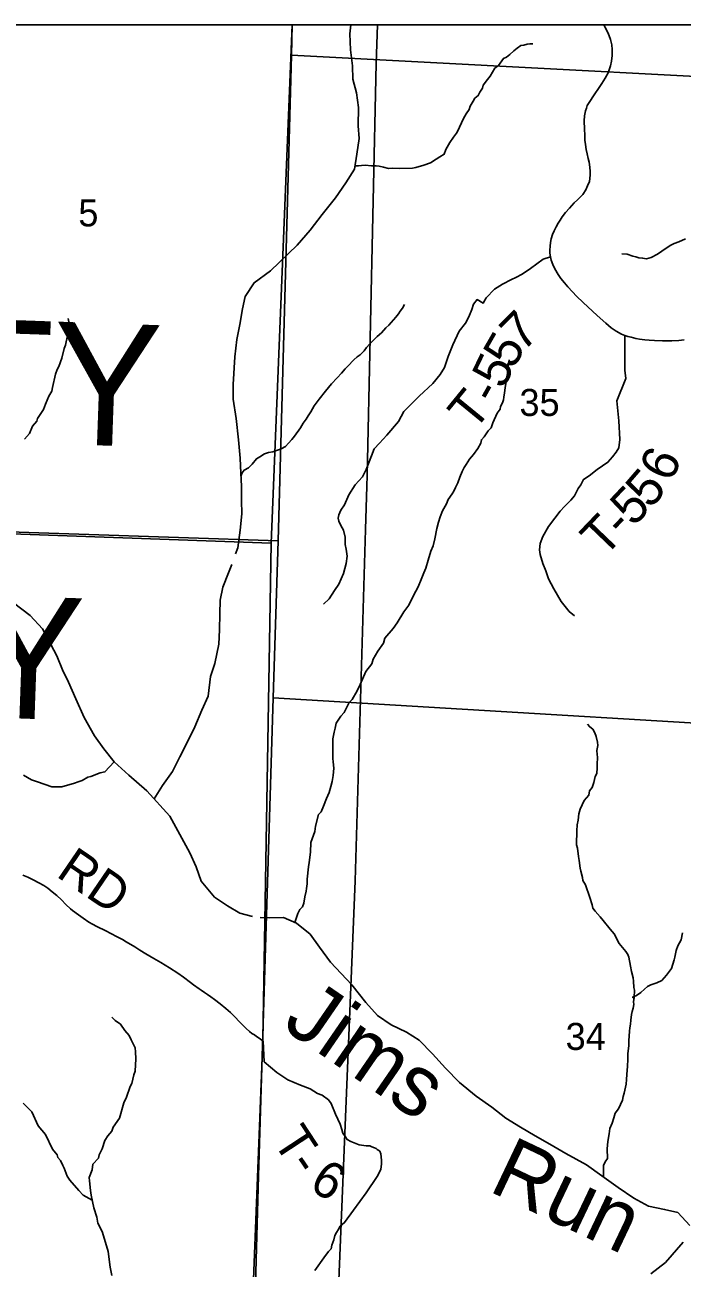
# Model space of a CAD drawing. Extents: x 6.3 to 40.3, y 9 to 31.
# Drawn here: x 12.585 to 13.605, y 28.019 to 29.946 of the extents above; entities that cross this region are included whole.
import ezdxf

# ---------------------------------------------------------------- set-up
doc = ezdxf.new("R2010")
doc.units = 0
for name, color, linetype in [('Default', 7, 'Continuous'), ('GM_X_Corporation', 7, 'Continuous'), ('GM_X_County_Text', 7, 'Continuous'), ('GM_X_Minor_River', 7, 'Continuous'), ('GM_X_Minor_River_Text', 7, 'Continuous'), ('GM_X_Section', 7, 'Continuous'), ('GM_X_Section_Text', 7, 'Continuous'), ('GM_X_State_Route', 7, 'Continuous'), ('GM_X_Township_Road', 7, 'Continuous'), ('GM_X_Township_Road_Text', 7, 'Continuous'), ('SH_Cut_Line', 7, 'Continuous'), ('SH_Data', 7, 'Continuous')]:
    doc.layers.add(name, color=color, linetype=linetype)

msp = doc.modelspace()

# ---------------------------------------------------------------- linework, layer by layer
at = {"layer": 'Default'}
for points in [[(13.1323, 29.9457), (8.4446, 29.9457), (8.4446, 27.9161), (8.9627, 27.9002), (9.9314, 27.8681), (10.145, 27.8635), (10.7129, 27.8423), (11.7175, 27.8106), (12.5872, 27.7766), (13.0625, 27.76), (13.0974, 28.6191), (13.1136, 29.1637), (13.1156, 29.231), (13.116, 29.2473), (13.13, 29.8856)], [(12.9998, 29.9457), (8.4446, 29.9457), (8.4446, 29.2958), (8.8673, 29.2829), (9.8361, 29.2507), (10.0496, 29.2462), (10.6176, 29.225), (11.6221, 29.1933), (12.4918, 29.1593), (12.9672, 29.1426)]]:
    msp.add_lwpolyline(points, close=True, dxfattribs=at)
for points in [[(13.8699, 27.9843), (13.9229, 28.0334), (14.1255, 28.1814), (14.1838, 28.2048), (14.2088, 28.2297), (14.3175, 28.3072), (14.3656, 28.3529), (14.5068, 28.5239), (14.7136, 28.6814), (14.8068, 28.7324), (14.9534, 28.8297), (15.2353, 29.0934), (15.2446, 29.1038), (15.2446, 29.9457), (12.9998, 29.9457), (12.9672, 29.1426), (12.9544, 28.3711), (12.9197, 27.4857)], [(15.2446, 27.6302), (15.2446, 29.9457), (13.1323, 29.9457), (13.13, 29.8856), (13.116, 29.2473), (13.1156, 29.231), (13.1136, 29.1637), (13.0974, 28.6191), (13.0625, 27.76)], [(12.5156, 26.6082), (12.5871, 26.6738), (12.6705, 26.7404), (12.7595, 26.8013), (12.8444, 26.8649), (12.9035, 26.9144), (12.9197, 27.4857), (12.9544, 28.3711), (12.9672, 29.1426), (12.4918, 29.1593)]]:
    msp.add_lwpolyline(points, dxfattribs=at)
at = {"layer": 'GM_X_Corporation'}
for points in [[(13, 29.9457), (12.3853, 29.9457), (12.3591, 29.1669), (12.9779, 29.1462), (12.9985, 29.8988)], [(13.9997, 29.9457), (13, 29.9457), (12.9985, 29.8988), (13.9983, 29.8461)]]:
    msp.add_lwpolyline(points, close=True, dxfattribs=at)
at = {"layer": 'GM_X_Minor_River'}
for points in [[(12.9121, 29.1259), (12.9155, 29.1352), (12.9193, 29.1628), (12.9216, 29.1881), (12.9212, 29.2088), (12.9212, 29.2307), (12.9201, 29.2508), (12.9193, 29.2742), (12.9167, 29.3025), (12.9129, 29.3357), (12.9084, 29.3655), (12.9084, 29.3886), (12.911, 29.4312), (12.914, 29.458), (12.9186, 29.4814), (12.9228, 29.5056), (12.9269, 29.5248), (12.9406, 29.546), (12.9663, 29.5645), (13.0076, 29.6045), (13.0276, 29.6275), (13.0462, 29.6517), (13.067, 29.6777), (13.0829, 29.7008), (13.0962, 29.7219), (13.1003, 29.7453), (13.1037, 29.7698), (13.1022, 29.7891), (13.1026, 29.8178), (13.0996, 29.8404), (13.0939, 29.8616), (13.0931, 29.882), (13.0901, 29.9069), (13.0893, 29.9318), (13.0907, 29.9457)], [(13.0971, 29.7273), (13.0973, 29.7274), (13.1026, 29.7275), (13.1075, 29.728), (13.1132, 29.7281), (13.1227, 29.7272), (13.1299, 29.727), (13.1349, 29.7267), (13.1413, 29.725), (13.1494, 29.7232), (13.1547, 29.7234), (13.1664, 29.7232), (13.1865, 29.7237), (13.1918, 29.7246), (13.2039, 29.7283), (13.2141, 29.7319), (13.223, 29.7374), (13.229, 29.7414), (13.2354, 29.7453), (13.2383, 29.7526), (13.2441, 29.7634), (13.25, 29.7715), (13.2548, 29.7777), (13.2573, 29.7827), (13.2591, 29.7873), (13.2624, 29.7938), (13.2657, 29.8007), (13.2697, 29.808), (13.2745, 29.8146), (13.2759, 29.8196), (13.2806, 29.8276), (13.2832, 29.8319), (13.2884, 29.8362), (13.291, 29.8412), (13.295, 29.8477), (13.296, 29.8523), (13.3027, 29.8608), (13.3071, 29.8662), (13.3141, 29.8785), (13.3197, 29.8825), (13.3274, 29.8937), (13.3323, 29.8957), (13.3375, 29.9), (13.3434, 29.9054), (13.349, 29.9097), (13.3543, 29.9136), (13.3592, 29.9145), (13.3641, 29.9158), (13.3683, 29.9162), (13.3732, 29.9163)], [(13.6098, 29.6139), (13.5993, 29.6095), (13.5925, 29.6067), (13.5861, 29.6039), (13.5734, 29.5949), (13.5663, 29.5902), (13.5566, 29.5854), (13.5494, 29.5829), (13.5433, 29.5843), (13.5376, 29.5846), (13.533, 29.586), (13.5281, 29.5874), (13.5196, 29.5902), (13.5113, 29.5908)], [(12.9203, 29.2462), (12.9221, 29.2515), (12.9251, 29.2557), (12.9318, 29.2593), (12.9378, 29.2648), (12.9444, 29.2733), (12.9497, 29.2764), (12.9568, 29.2808), (12.9632, 29.2828), (12.97, 29.2841), (12.9772, 29.2866), (12.9828, 29.2886), (12.9896, 29.2925), (12.994, 29.2972), (12.9992, 29.303), (13.0036, 29.3084), (13.0125, 29.3212), (13.0168, 29.3285), (13.0213, 29.3347), (13.0246, 29.3397), (13.0286, 29.3459), (13.0337, 29.3551), (13.0415, 29.3655), (13.0514, 29.3779), (13.061, 29.3895), (13.0696, 29.3988), (13.0763, 29.4058), (13.0818, 29.4124), (13.0859, 29.4167), (13.0952, 29.4264), (13.1007, 29.4315), (13.1052, 29.4346), (13.1112, 29.4404), (13.1152, 29.4455), (13.1204, 29.4513), (13.1315, 29.4629), (13.1383, 29.4684), (13.1449, 29.4762), (13.1498, 29.4801), (13.1605, 29.4929), (13.1649, 29.4979), (13.1675, 29.5021), (13.1708, 29.5068), (13.1741, 29.5122)], [(12.5844, 29.3035), (12.5921, 29.3125), (12.5968, 29.3236), (12.6039, 29.3313), (12.6049, 29.3355), (12.6141, 29.3494), (12.6173, 29.3579), (12.6224, 29.3701), (12.6271, 29.3778), (12.6278, 29.3839), (12.6326, 29.4042), (12.6351, 29.4118), (12.6381, 29.4165), (12.6423, 29.4291), (12.6462, 29.4444), (12.648, 29.4494), (12.6514, 29.4643), (12.6532, 29.4719), (12.6538, 29.4765), (12.6537, 29.4807), (12.6532, 29.4856), (12.6524, 29.4905)], [(13.004, 28.5548), (13.0088, 28.5685), (13.0117, 28.5747), (13.0158, 28.5786), (13.018, 28.5843), (13.0192, 28.5946), (13.0217, 28.603), (13.022, 28.6072), (13.023, 28.6144), (13.0232, 28.6217), (13.0251, 28.6407), (13.0261, 28.6476), (13.028, 28.6636), (13.0288, 28.6784), (13.0349, 28.6957), (13.0358, 28.7041), (13.0404, 28.7217), (13.0448, 28.7263), (13.0484, 28.7351), (13.0531, 28.7467), (13.0571, 28.7559), (13.0599, 28.7651), (13.0616, 28.7731), (13.0633, 28.7822), (13.0642, 28.7937), (13.0636, 28.8035), (13.0631, 28.8088), (13.0628, 28.8267), (13.0629, 28.8392), (13.0649, 28.8496), (13.0663, 28.856), (13.068, 28.8637), (13.0754, 28.8741), (13.0806, 28.8799), (13.0882, 28.8953), (13.0926, 28.9), (13.1007, 28.9135), (13.1054, 28.9234), (13.1141, 28.9434), (13.1233, 28.9554), (13.1254, 28.9627), (13.1328, 28.975), (13.1412, 28.9873), (13.1437, 28.995), (13.1563, 29.0101), (13.1625, 29.019), (13.1732, 29.0363), (13.1809, 29.0464), (13.1882, 29.0614), (13.1951, 29.0748), (13.1998, 29.0863), (13.2041, 29.0963), (13.207, 29.1036), (13.2105, 29.1162), (13.2151, 29.13), (13.2187, 29.1385), (13.2208, 29.1492), (13.2242, 29.1652), (13.227, 29.1751), (13.2291, 29.1832), (13.2331, 29.1924), (13.2393, 29.2035), (13.2415, 29.21), (13.2477, 29.2189), (13.2507, 29.2232), (13.2532, 29.2286), (13.2565, 29.2358), (13.2597, 29.245), (13.2633, 29.2535), (13.2666, 29.2596), (13.2695, 29.2646), (13.2746, 29.2727), (13.2809, 29.2801), (13.2879, 29.289), (13.2923, 29.2975), (13.2933, 29.3028), (13.2974, 29.3075), (13.304, 29.3167), (13.3085, 29.3214), (13.311, 29.329), (13.3175, 29.344), (13.3223, 29.3502), (13.3229, 29.3544), (13.3258, 29.3602), (13.3276, 29.3644), (13.3279, 29.3689), (13.3293, 29.3754), (13.3303, 29.3831), (13.3313, 29.3899), (13.3322, 29.3975), (13.3336, 29.4056), (13.3338, 29.4105), (13.3361, 29.4265)], [(12.7856, 28.7463), (12.7985, 28.7667), (12.814, 28.7886), (12.8254, 28.8112), (12.8383, 28.8365), (12.8489, 28.8577), (12.8595, 28.8834), (12.8697, 28.9053), (12.8731, 28.9358), (12.8799, 28.9562), (12.886, 28.9857), (12.8871, 29.008), (12.8875, 29.0329), (12.8879, 29.054), (12.892, 29.0744), (12.9011, 29.0963), (12.906, 29.1096)], [(12.9381, 28.5637), (12.9188, 28.5688), (12.8995, 28.5805), (12.8795, 28.5937), (12.8587, 28.6186), (12.8511, 28.6409), (12.8409, 28.6624), (12.8257, 28.6908), (12.8098, 28.7195), (12.7746, 28.7584), (12.7466, 28.7829), (12.7239, 28.8037), (12.7076, 28.8237), (12.6933, 28.8441), (12.6774, 28.8724), (12.6641, 28.9011), (12.6528, 28.9272), (12.6437, 28.9464), (12.635, 28.9679), (12.6123, 29.0098), (12.5934, 29.0302), (12.5676, 29.0502)], [(13.4826, 28.1602), (13.4826, 28.1781), (13.4851, 28.1835), (13.4888, 28.1889), (13.4885, 28.2037), (13.4894, 28.2151), (13.4914, 28.2273), (13.4924, 28.2353), (13.496, 28.2438), (13.4985, 28.2518), (13.501, 28.2591), (13.5061, 28.266), (13.5123, 28.2791), (13.5133, 28.2848), (13.5147, 28.2902), (13.5178, 28.3039), (13.5184, 28.3112), (13.5192, 28.326), (13.5199, 28.331), (13.5204, 28.3432), (13.5206, 28.3512), (13.5218, 28.3641), (13.522, 28.3713), (13.5228, 28.3862), (13.5235, 28.3911), (13.5245, 28.3972), (13.5251, 28.4033), (13.5261, 28.4121), (13.5271, 28.4167), (13.5289, 28.4217), (13.5295, 28.4274), (13.5294, 28.4316), (13.5304, 28.4384), (13.5306, 28.4498), (13.5297, 28.454), (13.5291, 28.4639), (13.5286, 28.4688), (13.5261, 28.4786), (13.5248, 28.487), (13.5222, 28.501), (13.5202, 28.5051), (13.5171, 28.5096), (13.507, 28.5219), (13.4994, 28.537), (13.4932, 28.544), (13.4823, 28.5575), (13.4776, 28.5635), (13.4698, 28.572), (13.4659, 28.5769), (13.4651, 28.5822), (13.4614, 28.5935), (13.4545, 28.6128), (13.4506, 28.6199), (13.4501, 28.6244), (13.4476, 28.6339), (13.4464, 28.6388), (13.445, 28.6506), (13.4441, 28.657), (13.4423, 28.6699), (13.441, 28.6752), (13.4409, 28.6809), (13.4414, 28.6912), (13.4413, 28.6968), (13.4419, 28.706), (13.4432, 28.7132), (13.4445, 28.7228), (13.4466, 28.7304), (13.4528, 28.7439), (13.4598, 28.752), (13.4612, 28.7585), (13.4649, 28.7639), (13.4678, 28.7716), (13.4698, 28.7811), (13.4724, 28.7854), (13.473, 28.7941), (13.4728, 28.7994), (13.4733, 28.8109), (13.4729, 28.815), (13.4724, 28.8211), (13.4737, 28.8291), (13.4736, 28.834), (13.4711, 28.8427), (13.4691, 28.8484), (13.4659, 28.8544), (13.4613, 28.8577), (13.4578, 28.8622)], [(12.7239, 28.8037), (12.7094, 28.788), (12.7019, 28.7864), (12.6875, 28.7809), (12.6826, 28.7797), (12.6743, 28.7747), (12.6678, 28.7727), (12.6622, 28.7707), (12.6425, 28.7648), (12.6269, 28.765), (12.6048, 28.7728), (12.5957, 28.7757), (12.5831, 28.7828)], [(13.6168, 28.0849), (13.5979, 28.1053), (13.5775, 28.1099), (13.5525, 28.1152), (13.5298, 28.1276), (13.5052, 28.1439), (13.4802, 28.162), (13.4563, 28.179), (13.4245, 28.1964), (13.3992, 28.2111), (13.3768, 28.2239), (13.3537, 28.2372), (13.3314, 28.2515), (13.3095, 28.2685), (13.2852, 28.2855), (13.2595, 28.3067), (13.2375, 28.3286), (13.2175, 28.3512), (13.197, 28.3724), (13.177, 28.3848), (13.1531, 28.3958), (13.1323, 28.4105), (13.1142, 28.4305), (13.0922, 28.4581), (13.0593, 28.4929), (13.0422, 28.5163), (13.0279, 28.5363), (13.0067, 28.5537), (12.9862, 28.5624), (12.9643, 28.562), (12.9501, 28.5624)], [(13.5302, 28.4371), (13.5278, 28.4388), (13.5338, 28.4416), (13.5405, 28.4459), (13.5461, 28.451), (13.5509, 28.4552), (13.5562, 28.458), (13.5656, 28.4609), (13.5731, 28.4645), (13.5802, 28.473), (13.5879, 28.4831), (13.5925, 28.4965), (13.5932, 28.5007), (13.5956, 28.5114), (13.5978, 28.5183), (13.6029, 28.5275), (13.6053, 28.5386)], [(12.7322, 28.2513), (12.7388, 28.275), (12.7428, 28.2837), (12.7487, 28.3005), (12.751, 28.3051), (12.7542, 28.3184), (12.7561, 28.3242), (12.7574, 28.3435), (12.7569, 28.3542), (12.7561, 28.3603), (12.7499, 28.3727), (12.7468, 28.3792), (12.7402, 28.3874), (12.7333, 28.3972), (12.7253, 28.4025), (12.7203, 28.4077)], [(12.6897, 28.1245), (12.6757, 28.1322), (12.6688, 28.139), (12.6549, 28.1555), (12.6507, 28.1612), (12.646, 28.1737), (12.6441, 28.1782), (12.6402, 28.1858), (12.6364, 28.1903), (12.6352, 28.1945), (12.6279, 28.2035), (12.6174, 28.2262), (12.6058, 28.2397), (12.5961, 28.2613), (12.5827, 28.2744)], [(12.7203, 28.0073), (12.7175, 28.0206), (12.7142, 28.0448), (12.7103, 28.0585), (12.7051, 28.0759), (12.6982, 28.0887), (12.6969, 28.0978), (12.6922, 28.1122), (12.6882, 28.1319), (12.687, 28.1392), (12.6853, 28.154), (12.6849, 28.1596), (12.6893, 28.1711), (12.6904, 28.1798), (12.6994, 28.1894), (12.7005, 28.1944), (12.7049, 28.2036), (12.7094, 28.2165), (12.7138, 28.2242), (12.7202, 28.2314), (12.7221, 28.2375), (12.7322, 28.2513)], [(13.5559, 28.0102), (13.5786, 28.0279), (13.6062, 28.0589)]]:
    msp.add_lwpolyline(points, dxfattribs=at)
at = {"layer": 'GM_X_Section'}
for points in [[(12.9985, 29.8988), (13.9983, 29.8461), (13.9707, 28.8429), (12.9705, 28.903), (12.9779, 29.1462)], [(13.9707, 28.8429), (13.9488, 28.0971), (13.9414, 28.0891), (13.9298, 28.0809), (13.9193, 28.0713), (13.9144, 28.0682), (13.9073, 28.0646), (13.887, 28.0511), (13.8713, 28.041), (13.8566, 28.0312), (13.8409, 28.0192), (13.8282, 28.0088), (13.8129, 27.9945), (13.7935, 27.9757), (13.7752, 27.9591), (13.7666, 27.9502), (13.751, 27.931), (13.7384, 27.9153), (13.7272, 27.9015), (13.7153, 27.8854), (13.6983, 27.8601), (12.9402, 27.9008), (12.9478, 28.1619), (12.9705, 28.903)]]:
    msp.add_lwpolyline(points, close=True, dxfattribs=at)
at = {"layer": 'GM_X_State_Route'}
msp.add_lwpolyline([(13.608, 29.4574), (13.5997, 29.4568), (13.5887, 29.4559), (13.574, 29.4559), (13.5618, 29.4563), (13.5536, 29.457), (13.5466, 29.4576), (13.5386, 29.4587), (13.5329, 29.4599), (13.5255, 29.4615), (13.5202, 29.463), (13.516, 29.4644), (13.5104, 29.4663), (13.5023, 29.4708), (13.4948, 29.4763), (13.4861, 29.4835), (13.4727, 29.4953), (13.4512, 29.5157), (13.4406, 29.5255), (13.4347, 29.5318), (13.4273, 29.5396), (13.422, 29.546), (13.4166, 29.5525), (13.4125, 29.5586), (13.4071, 29.5676), (13.4041, 29.5742), (13.4016, 29.5813), (13.4004, 29.5863), (13.3996, 29.5921), (13.3993, 29.5968), (13.4001, 29.6027), (13.4007, 29.6086), (13.4016, 29.6142), (13.4037, 29.6206), (13.4061, 29.6267), (13.4091, 29.6328), (13.4122, 29.6382), (13.4152, 29.6429), (13.4186, 29.648), (13.4239, 29.6549), (13.4301, 29.6614), (13.4373, 29.6697), (13.4422, 29.6745), (13.4506, 29.683), (13.4551, 29.6901), (13.458, 29.6965), (13.461, 29.7031), (13.4619, 29.7127), (13.4619, 29.7183), (13.4613, 29.7253), (13.4602, 29.7327), (13.4587, 29.7386), (13.4571, 29.7461), (13.4559, 29.7528), (13.4545, 29.7603), (13.4535, 29.7668), (13.4535, 29.7749), (13.4532, 29.7841), (13.4529, 29.7972), (13.4531, 29.8047), (13.4545, 29.8123), (13.4562, 29.8167), (13.4574, 29.8207), (13.4604, 29.8254), (13.4682, 29.8374), (13.476, 29.8486), (13.48, 29.8549), (13.4852, 29.863), (13.4897, 29.8714), (13.4934, 29.8823), (13.4951, 29.8895), (13.4962, 29.898), (13.4961, 29.9074), (13.4956, 29.9149), (13.4934, 29.9231), (13.4897, 29.9331), (13.4847, 29.9428), (13.483, 29.9457)], dxfattribs=at)
at = {"layer": 'GM_X_Township_Road'}
for points in [[(13.4004, 29.5863), (13.3892, 29.5826), (13.3694, 29.5681), (13.3563, 29.5595), (13.3468, 29.5544), (13.3402, 29.5513), (13.3258, 29.5438), (13.3137, 29.5363), (13.3008, 29.5226), (13.2958, 29.5142), (13.2866, 29.52), (13.281, 29.513), (13.2782, 29.5046), (13.274, 29.4934), (13.2684, 29.4835), (13.2586, 29.4709), (13.2488, 29.4499), (13.2418, 29.4317), (13.2362, 29.4149), (13.2292, 29.4037), (13.218, 29.3897), (13.197, 29.3701), (13.183, 29.3561), (13.1731, 29.3463), (13.1648, 29.3309), (13.1466, 29.3099), (13.1353, 29.2973), (13.127, 29.2889), (13.1227, 29.2776), (13.1143, 29.2566), (13.1087, 29.2454), (13.0975, 29.2328), (13.0877, 29.2174), (13.0807, 29.202), (13.0751, 29.1936), (13.0723, 29.1866), (13.0709, 29.181), (13.0723, 29.1768), (13.0751, 29.1698), (13.0793, 29.1628), (13.0821, 29.1516), (13.0821, 29.1404), (13.0835, 29.1334), (13.0849, 29.1222), (13.0835, 29.111), (13.0793, 29.0956), (13.0723, 29.0788), (13.0653, 29.0689), (13.0569, 29.0563), (13.0485, 29.0479)], [(13.4378, 29.0297), (13.4294, 29.0367), (13.4168, 29.0522), (13.4056, 29.0718), (13.3972, 29.0872), (13.393, 29.0998), (13.3888, 29.111), (13.3846, 29.125), (13.3832, 29.132), (13.3846, 29.1418), (13.3888, 29.153), (13.3972, 29.1684), (13.407, 29.181), (13.4154, 29.1922), (13.4224, 29.1992), (13.4322, 29.2091), (13.4378, 29.216), (13.4434, 29.2273), (13.4476, 29.2328), (13.4518, 29.2413), (13.4602, 29.2469), (13.4728, 29.2567), (13.4812, 29.2623), (13.4896, 29.2679), (13.4966, 29.2763), (13.5022, 29.2833), (13.5064, 29.2903), (13.5078, 29.3029), (13.5064, 29.3323), (13.5036, 29.3631), (13.5173, 29.3979), (13.516, 29.4105), (13.516, 29.4644)], [(12.9546, 28.3705), (12.9488, 28.3752), (12.9447, 28.3781), (12.9411, 28.3805), (12.9392, 28.3816), (12.9374, 28.3827), (12.9335, 28.3857), (12.9284, 28.3901), (12.9227, 28.3958), (12.9185, 28.4003), (12.9105, 28.4089), (12.9042, 28.4149), (12.8968, 28.4215), (12.8881, 28.4285), (12.8792, 28.4353), (12.8736, 28.4393), (12.8686, 28.4429), (12.864, 28.446), (12.8588, 28.4495), (12.8553, 28.452), (12.8468, 28.4582), (12.8423, 28.4615), (12.8313, 28.4696), (12.8222, 28.476), (12.8097, 28.4841), (12.796, 28.4927), (12.7853, 28.499), (12.773, 28.5062), (12.7634, 28.5119), (12.7555, 28.5167), (12.7422, 28.5246), (12.7364, 28.528), (12.7282, 28.5325), (12.7183, 28.5377), (12.7106, 28.5415), (12.6966, 28.5484), (12.6901, 28.5518), (12.6842, 28.5553), (12.6754, 28.5611), (12.6683, 28.5662), (12.6588, 28.5732), (12.6559, 28.5756), (12.6488, 28.5825), (12.6418, 28.5895), (12.6345, 28.5962), (12.6274, 28.6023), (12.6206, 28.6076), (12.6178, 28.6097), (12.6144, 28.6119), (12.607, 28.6163), (12.5982, 28.6209), (12.5897, 28.6249), (12.5822, 28.6279)], [(12.9546, 28.3705), (12.9565, 28.3387), (12.9761, 28.3219), (12.9929, 28.3107), (13.0125, 28.3023), (13.0279, 28.2967), (13.0391, 28.2897), (13.0461, 28.2869), (13.0559, 28.2799), (13.0601, 28.2743), (13.0671, 28.2575), (13.0741, 28.2421), (13.0769, 28.2336), (13.0783, 28.228), (13.0825, 28.2224), (13.0853, 28.2182), (13.0909, 28.2154), (13.1035, 28.2098), (13.1147, 28.2084), (13.1203, 28.2084), (13.1231, 28.207), (13.1273, 28.2056), (13.1301, 28.2042), (13.1315, 28.2028), (13.1343, 28.2014), (13.1357, 28.2), (13.1371, 28.1958), (13.1385, 28.186), (13.1385, 28.1804), (13.1371, 28.172), (13.1315, 28.1608), (13.1147, 28.1356), (13.0951, 28.109), (13.0811, 28.0894), (13.0741, 28.0837), (13.0713, 28.0781), (13.0685, 28.0739), (13.0657, 28.0697), (13.0643, 28.0627), (13.0615, 28.0543), (13.0601, 28.0487), (13.0559, 28.0445), (13.0489, 28.0347), (13.0349, 28.0151)]]:
    msp.add_lwpolyline(points, dxfattribs=at)
at = {"layer": 'SH_Cut_Line'}
for points in [[(13.8699, 27.9843), (13.9229, 28.0334), (14.1255, 28.1814), (14.1838, 28.2048), (14.2088, 28.2297), (14.3175, 28.3072), (14.3656, 28.3529), (14.5068, 28.5239), (14.7136, 28.6814), (14.8068, 28.7324), (14.9534, 28.8297), (15.2353, 29.0934), (15.2446, 29.1038), (15.2446, 29.9457), (8.4446, 29.9457)], [(12.4918, 29.1593), (12.9672, 29.1426), (12.9544, 28.3711), (12.9197, 27.4857)], [(12.5156, 26.6082), (12.5871, 26.6738), (12.6705, 26.7404), (12.7595, 26.8013), (12.8444, 26.8649), (12.9035, 26.9144), (12.9197, 27.4857), (12.9544, 28.3711), (12.9672, 29.1426), (12.4918, 29.1593)]]:
    msp.add_lwpolyline(points, dxfattribs=at)
at = {"layer": 'SH_Data'}
msp.add_line((8.4446, 29.9457), (15.2446, 29.9457), dxfattribs=at)

# ---------------------------------------------------------------- texts
at = {"layer": 'GM_X_County_Text'}
for s, p in [('MONROE COUNTY', (10.5153, 29.3712)), ('WASHINGTON COUNTY', (9.7904, 28.9692))]:
    msp.add_text(s, height=0.189394, rotation=357.9773, dxfattribs=at).set_placement(p)
at = {"layer": 'GM_X_Minor_River_Text'}
for s, height, rotation, p in [('Jims', 0.09471, 325.4627, (12.9821, 28.3924)), ('Run', 0.0947, 334.5753, (13.3022, 28.1394))]:
    msp.add_text(s, height=height, rotation=rotation, dxfattribs=at).set_placement(p)
at = {"layer": 'GM_X_Section_Text'}
for s, height, p in [('5', 0.0419, (12.6681, 29.6334)), ('35', 0.04186, (13.3523, 29.3396)), ('34', 0.04186, (13.4239, 28.3571))]:
    msp.add_text(s, height=height, rotation=0, dxfattribs=at).set_placement(p)
at = {"layer": 'GM_X_Township_Road_Text'}
for s, height, rotation, p in [('7', 0.0568, 45.4637, (13.3573, 29.4375)), ('5', 0.0568, 60.0666, (13.3422, 29.4102)), ('5', 0.0568, 64.384, (13.3276, 29.3796)), ('T', 0.0568, 50.7659, (13.2815, 29.3142)), ('-', 0.0568, 60.5635, (13.3142, 29.3557)), ('6', 0.0568, 65.1445, (13.5874, 29.2351)), ('5', 0.0568, 49.2941, (13.5553, 29.1942)), ('5', 0.0568, 46.5767, (13.5292, 29.1666)), ('T', 0.0568, 46.2092, (13.4834, 29.1188)), ('-', 0.0568, 46.2845, (13.5129, 29.1495)), ('RD', 0.05682, 325.6672, (12.632, 28.6271)), ('T', 0.0568, 303.2663, (12.9685, 28.2159)), ('-', 0.0568, 304.2363, (12.9923, 28.1796)), ('6', 0.0568, 328.1829, (13.0239, 28.1427))]:
    msp.add_text(s, height=height, rotation=rotation, dxfattribs=at).set_placement(p)

doc.saveas('drawing.dxf')
